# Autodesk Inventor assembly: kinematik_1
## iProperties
Created: 2007-11
Part Number: kinematik_1
Document SubType Name: Assembly
Designer: martin
Manufacturer: Standard
Standards Organization: Custom
Author: martin
